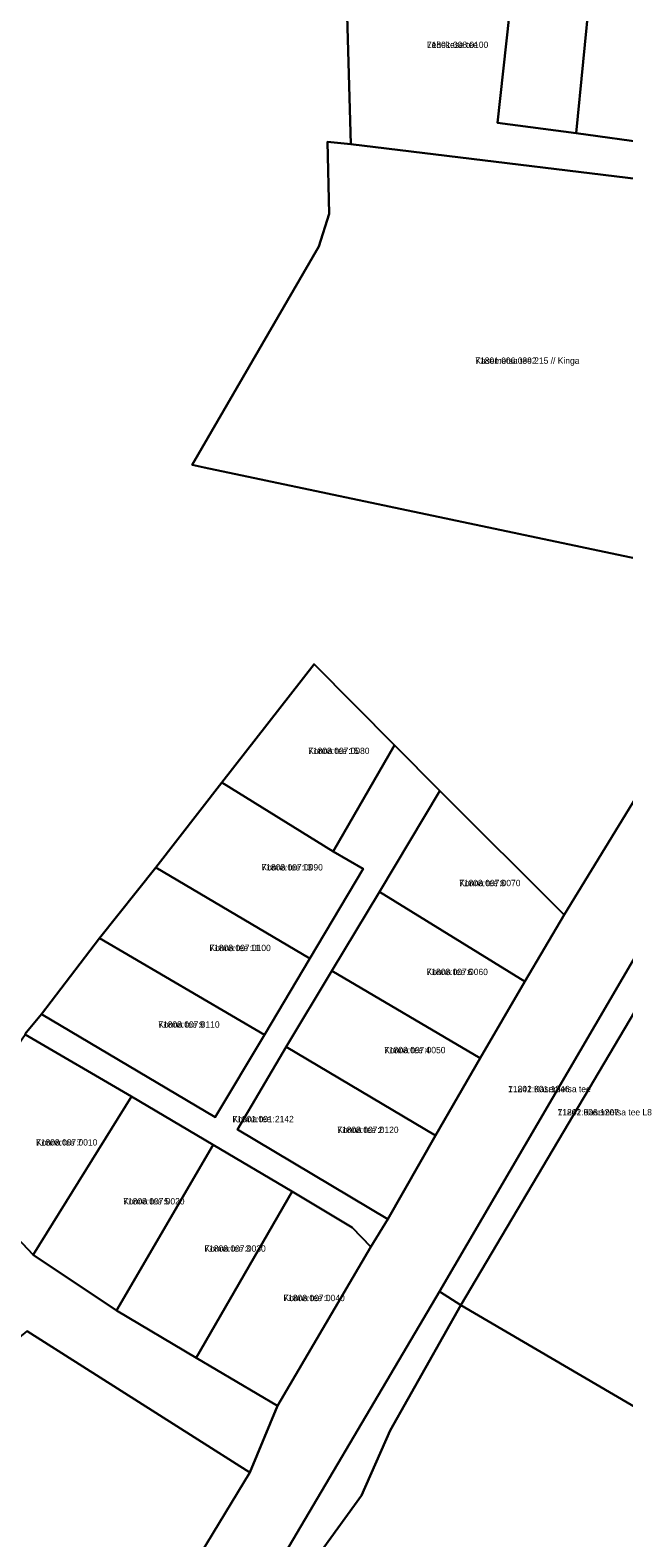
# Model space of a CAD drawing. Extents: x 529768 to 552006, y 6562269 to 6580975.
# Drawn here: x 537471.9 to 537612.3, y 6569320.5 to 6569676.9 of the extents above; entities that cross this region are included whole.
import ezdxf

# ---------------------------------------------------------------- set-up
doc = ezdxf.new("R2010")
doc.units = 0
for name, color, linetype in [('L_AADRESS', 7, 'Continuous'), ('PIIR', 7, 'Continuous'), ('TUNNUS', 7, 'Continuous')]:
    doc.layers.add(name, color=color, linetype=linetype)

msp = doc.modelspace()

# ---------------------------------------------------------------- linework, layer by layer
at = {"layer": 'PIIR'}
for points in [[(537281.43, 6569019.46), (537368.89, 6569121.58), (537420.6, 6569181.09), (537438.26, 6569204.93), (537445.15, 6569209.46), (537456.97, 6569225.74), (537523.87, 6569335.93), (537530.38, 6569351.64), (537552.48, 6569389.3), (537556.5, 6569395.83), (537567.78, 6569415.59), (537578.32, 6569433.84), (537588.9, 6569451.99), (537598.21, 6569467.74), (537645.8, 6569545.54), (537653.92, 6569559.3), (537664.42, 6569572.88), (537699.62, 6569634.71), (537702.59, 6569639.82), (537731.22, 6569689.57), (537747.58, 6569702.72), (538032.41, 6569935.34), (538189.88, 6570063.68)], [(537546.01, 6569710.64), (537547.78, 6569649.91), (537542.21, 6569650.49), (537542.63, 6569633.45), (537540.15, 6569625.74), (537510.21, 6569574.1), (537513.09, 6569573.49), (537645.8, 6569545.54), (537598.21, 6569467.74), (537568.78, 6569497.06), (537558.09, 6569507.89), (537539.11, 6569527.02), (537517.23, 6569499.01), (537501.67, 6569478.93), (537488.34, 6569462.21), (537474.6, 6569444.23), (537471.03, 6569440)], [(537622.11, 6569470.11), (537568.68, 6569378.74), (537478.05, 6569225.23), (537473.1, 6569217.08), (537463.95, 6569204.19), (537434.3, 6569169.03), (537381.02, 6569108.28), (537348.18, 6569069.26)], [(537721.35, 6569289.12), (537573.72, 6569375.48), (537624.58, 6569461.25)], [(537450.7, 6569410.53), (537472.62, 6569387.4), (537492.35, 6569374.23), (537511.14, 6569363.02), (537530.38, 6569351.64), (537523.87, 6569335.93), (537471.2, 6569369.35)]]:
    msp.add_lwpolyline(points, dxfattribs=at)
for points in [[(537635.95, 6569639.23), (537547.78, 6569649.91), (537546.01, 6569710.64), (537587.98, 6569705.34), (537582.4, 6569654.98), (537601.05, 6569652.57), (537619.24, 6569650.03), (537637.33, 6569647.48), (537655.29, 6569645.19), (537672.82, 6569643.09), (537690.57, 6569641.16), (537702.59, 6569639.82), (537699.62, 6569634.71), (537672.69, 6569634.96), (537654.17, 6569636.94)], [(537582.4, 6569654.98), (537587.98, 6569705.34), (537605.99, 6569703.24), (537601.05, 6569652.57)], [(537601.05, 6569652.57), (537605.99, 6569703.24), (537625.89, 6569700.98), (537619.24, 6569650.03)], [(537547.78, 6569649.91), (537635.95, 6569639.23), (537627.87, 6569580.82), (537643.65, 6569577.43), (537661.73, 6569573.54), (537664.42, 6569572.88), (537653.92, 6569559.3), (537645.8, 6569545.54), (537513.09, 6569573.49), (537510.21, 6569574.1), (537540.15, 6569625.74), (537542.63, 6569633.45), (537542.21, 6569650.49)], [(537558.09, 6569507.89), (537543.58, 6569482.7), (537517.23, 6569499.01), (537539.11, 6569527.02)], [(537470.72, 6569439.43), (537471.03, 6569440), (537474.6, 6569444.23), (537515.68, 6569419.92), (537527.29, 6569439.41), (537538.02, 6569457.44), (537550.64, 6569478.65), (537543.58, 6569482.7), (537558.09, 6569507.89), (537568.78, 6569497.06), (537554.51, 6569473.16), (537543.21, 6569454.47), (537532.42, 6569436.52), (537520.93, 6569416.97), (537556.5, 6569395.83), (537552.48, 6569389.3), (537548.03, 6569393.84), (537533.88, 6569402.34), (537515.22, 6569413.37), (537495.89, 6569424.8)], [(537517.23, 6569499.01), (537543.58, 6569482.7), (537550.64, 6569478.65), (537538.02, 6569457.44), (537501.67, 6569478.93)], [(537568.78, 6569497.06), (537598.21, 6569467.74), (537588.9, 6569451.99), (537554.51, 6569473.16)], [(537501.67, 6569478.93), (537538.02, 6569457.44), (537527.29, 6569439.41), (537488.34, 6569462.21)], [(537554.51, 6569473.16), (537588.9, 6569451.99), (537578.32, 6569433.84), (537543.21, 6569454.47)], [(537622.11, 6569470.11), (537624.58, 6569461.25), (537573.72, 6569375.48), (537568.68, 6569378.74)], [(537488.34, 6569462.21), (537527.29, 6569439.41), (537515.68, 6569419.92), (537474.6, 6569444.23)], [(537578.32, 6569433.84), (537567.78, 6569415.59), (537532.42, 6569436.52), (537543.21, 6569454.47)], [(537495.89, 6569424.8), (537472.62, 6569387.4), (537450.7, 6569410.53), (537470.72, 6569439.43)], [(537532.42, 6569436.52), (537567.78, 6569415.59), (537556.5, 6569395.83), (537520.93, 6569416.97)], [(537472.62, 6569387.4), (537495.89, 6569424.8), (537515.22, 6569413.37), (537492.35, 6569374.23)], [(537492.35, 6569374.23), (537515.22, 6569413.37), (537533.88, 6569402.34), (537511.14, 6569363.02)], [(537511.14, 6569363.02), (537533.88, 6569402.34), (537548.03, 6569393.84), (537552.48, 6569389.3), (537530.38, 6569351.64)], [(537568.68, 6569378.74), (537573.72, 6569375.48), (537557.07, 6569345.82), (537550.3, 6569330.48), (537532.46, 6569305.9), (537483.59, 6569223.61), (537478.05, 6569225.23)], [(537573.72, 6569375.48), (537721.35, 6569289.12), (537724.42, 6569287.32), (537584.93, 6569195.2), (537580.98, 6569196.31), (537483.59, 6569223.61), (537532.46, 6569305.9), (537550.3, 6569330.48), (537557.07, 6569345.82)], [(537392.4, 6569272.37), (537420.72, 6569327.75), (537471.2, 6569369.35), (537523.87, 6569335.93), (537456.97, 6569225.74), (537428.48, 6569246.54)]]:
    msp.add_lwpolyline(points, close=True, dxfattribs=at)

# ---------------------------------------------------------------- texts
at = {"layer": 'L_AADRESS'}
for s, p in [('Lehekese tee', (537565.74, 6569672.68)), ('Kasemetsa tee 215 // Kinga', (537577.16, 6569598.01)), ('Konna tee 15', (537537.66, 6569505.76)), ('Konna tee 13', (537526.62, 6569478.23)), ('Konna tee 8', (537573.36, 6569474.52)), ('Konna tee 11', (537514.31, 6569459.17)), ('Konna tee 6', (537565.65, 6569453.5)), ('Konna tee 9', (537502.21, 6569441.07)), ('Konna tee 4', (537555.62, 6569435.03)), ('11242 Kasemetsa tee', (537584.95, 6569425.82)), ('Konna tee', (537519.75, 6569418.72)), ('11242 Kasemetsa tee L8', (537596.63, 6569420.33)), ('Konna tee 2', (537544.53, 6569416.17)), ('Konna tee 7', (537473.3, 6569413.21)), ('Konna tee 5', (537493.92, 6569399.28)), ('Konna tee 3', (537513.12, 6569388.1)), ('Konna tee 1', (537531.81, 6569376.42))]:
    msp.add_text(s, height=1.5, dxfattribs=at).set_placement(p)
at = {"layer": 'TUNNUS'}
for s, p in [('71801:008:0100', (537565.74, 6569672.68)), ('71801:006:0392', (537577.16, 6569598.01)), ('71808:007:0080', (537537.66, 6569505.76)), ('71808:007:0090', (537526.62, 6569478.23)), ('71808:007:0070', (537573.36, 6569474.52)), ('71808:007:0100', (537514.31, 6569459.17)), ('71808:007:0060', (537565.65, 6569453.5)), ('71808:007:0110', (537502.21, 6569441.07)), ('71808:007:0050', (537555.62, 6569435.03)), ('71801:001:1346', (537584.95, 6569425.82)), ('71801:001:2142', (537519.75, 6569418.72)), ('71801:006:1207', (537596.63, 6569420.33)), ('71808:007:0120', (537544.53, 6569416.17)), ('71808:007:0010', (537473.3, 6569413.21)), ('71808:007:0020', (537493.92, 6569399.28)), ('71808:007:0030', (537513.12, 6569388.1)), ('71808:007:0040', (537531.81, 6569376.42))]:
    msp.add_text(s, height=1.5, dxfattribs=at).set_placement(p)

doc.saveas('drawing.dxf')
